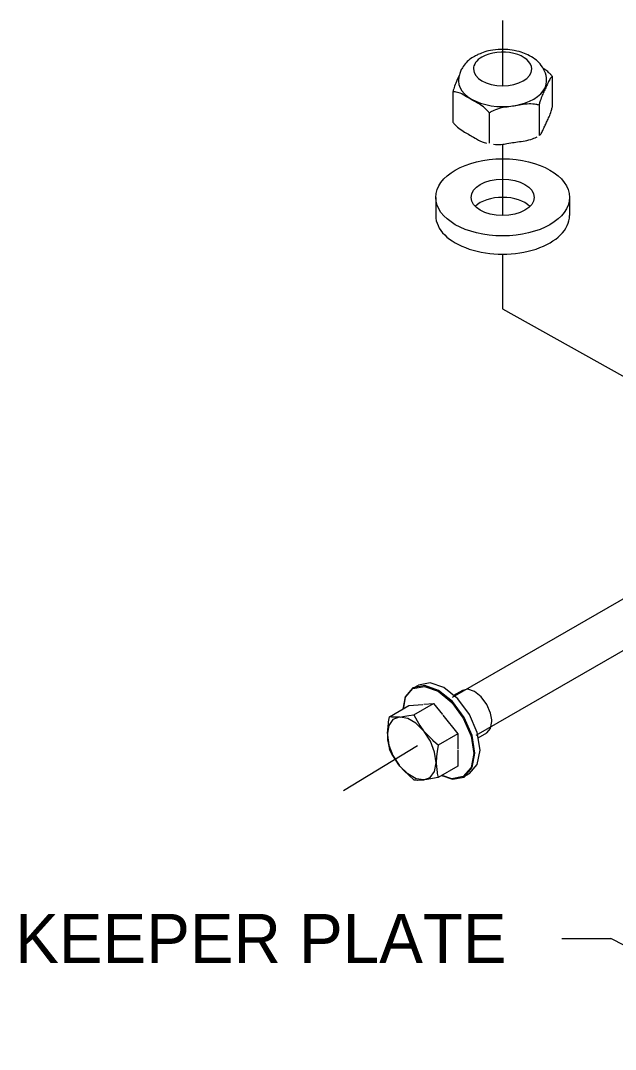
# Model space of a CAD drawing. Extents: x 99862 to 103151, y 99997 to 117076.
# Drawn here: x 101413.6 to 101608, y 116157.4 to 116493.6 of the extents above; entities that cross this region are included whole.
import ezdxf

# ---------------------------------------------------------------- set-up
doc = ezdxf.new("R2010")
doc.units = 0
for name, color, linetype in [('Level 12', 7, 'Continuous'), ('Level 13', 7, 'Continuous'), ('Level 15', 7, 'Continuous'), ('Level 20', 7, 'Continuous'), ('Level 3', 7, 'Continuous'), ('Level 5', 7, 'Continuous'), ('Level 9', 7, 'Continuous')]:
    doc.layers.add(name, color=color, linetype=linetype)

msp = doc.modelspace()

# ---------------------------------------------------------------- linework, layer by layer
at = {"layer": 'Level 12'}
for p, q in [((101587.37, 116465.38), (101587.37, 116475.29)), ((101554.87, 116470.27), (101554.87, 116460.36)), ((101583.02, 116465.91), (101583.02, 116456)), ((101566.77, 116463.4), (101566.77, 116453.49)), ((101549.27, 116435.8), (101549.27, 116429.85)), ((101592.97, 116435.8), (101592.97, 116429.85))]:
    msp.add_line(p, q, dxfattribs=at)
for centre, major_axis, start_param, end_param in [((101571.12, 116477.74), (9.54, 0), 2.356194, 3.141593), ((101571.12, 116477.74), (9.54, 0), 6.283185, 8.63938), ((101571.12, 116477.74), (9.54, 0), 3.141593, 6.283185), ((101571.12, 116473.77), (-14.39, 0), 0, 3.141593), ((101571.12, 116429.85), (-10.32, 0), 3.664192, 5.760586), ((101571.12, 116429.85), (-21.85, 0), 0, 3.141593)]:
    msp.add_ellipse(centre, major_axis=major_axis, ratio=0.57735, start_param=start_param, end_param=end_param, dxfattribs=at)
for major_axis in [(-21.85, 0), (-10.32, 0)]:
    msp.add_ellipse((101571.12, 116435.8), major_axis=major_axis, ratio=0.57735, dxfattribs=at)
for points in [[(101585.51, 116473.77), (101585.51, 116475.3), (101584.96, 116477.05), (101583.29, 116479.65), (101581.88, 116480.92), (101579.19, 116482.53), (101577.46, 116483.21), (101574.01, 116484.03), (101571.64, 116484.22), (101567.64, 116483.95), (101565.34, 116483.43), (101563.06, 116482.46), (101562.44, 116482.16), (101560.6, 116481.09), (101559.23, 116479.92), (101557.85, 116478), (101557.37, 116477.06), (101556.87, 116475.48), (101556.73, 116474.55), (101556.73, 116473.77)], [(101587.37, 116475.29), (101587.11, 116475.64), (101586.81, 116475.97), (101585.87, 116476.88), (101585.14, 116477.44), (101584.38, 116477.94)], [(101556.99, 116475.82), (101556.41, 116474.57), (101555.72, 116473.15), (101555.08, 116471.06), (101554.97, 116470.67), (101554.87, 116470.27)], [(101587.37, 116475.29), (101587.27, 116475.29), (101587.16, 116475.2), (101586.5, 116474.49), (101585.79, 116472.87), (101585.19, 116471.59), (101584.6, 116470.31), (101583.88, 116468.86), (101583.22, 116466.71), (101583.11, 116466.31), (101583.02, 116465.91)], [(101566.77, 116463.4), (101566.51, 116463.74), (101566.2, 116464.08), (101564.39, 116465.84), (101562.44, 116466.88), (101560.82, 116467.82), (101559.19, 116468.76), (101557.25, 116469.97), (101555.44, 116470.29), (101555.13, 116470.31), (101554.87, 116470.27)], [(101583.02, 116465.91), (101582.66, 116466.05), (101582.25, 116466.14), (101579.77, 116466.48), (101577.11, 116465.99), (101574.89, 116465.64), (101572.67, 116465.3), (101570.01, 116464.97), (101567.54, 116463.87), (101567.12, 116463.65), (101566.77, 116463.4)], [(101583.14, 116456.05), (101583.2, 116456.09), (101583.26, 116456.14), (101583.88, 116456.8), (101584.6, 116458.42), (101585.19, 116459.71), (101585.79, 116460.99), (101586.5, 116462.44), (101587.16, 116464.59), (101587.27, 116464.98), (101587.37, 116465.38)], [(101554.87, 116460.36), (101555.13, 116460.01), (101555.44, 116459.68), (101557.25, 116457.91), (101559.19, 116456.87), (101560.82, 116455.94), (101562.41, 116455.02), (101564.31, 116453.84), (101565.83, 116453.53)], [(101568.11, 116453.18), (101570.17, 116452.95), (101572.74, 116453.43), (101574.89, 116453.76), (101577.11, 116454.1), (101579.77, 116454.43), (101582.05, 116455.44), (101582.23, 116455.53), (101582.42, 116455.63)]]:
    msp.add_open_spline(points, degree=3, dxfattribs=at)
at = {"layer": 'Level 13'}
for p, q in [((101554.8, 116272.49), (101645.58, 116324.9)), ((101562.5, 116260.11), (101652.86, 116312.28))]:
    msp.add_line(p, q, dxfattribs=at)
at = {"layer": 'Level 15'}
for p, q in [((101571.12, 116493.56), (101571.12, 116472.23)), ((101571.12, 116465.46), (101571.12, 116465.01)), ((101571.12, 116453.22), (101571.12, 116429.84)), ((101571.12, 116417.24), (101571.12, 116399.4)), ((101519.18, 116241.97), (101543.31, 116256.68)), ((101590.44, 116193.67), (101606.44, 116193.67)), ((101676.74, 116157.42), (101606.44, 116193.67))]:
    msp.add_line(p, q, dxfattribs=at)
msp.add_lwpolyline([(101571.12, 116399.4), (101707.38, 116323.31)], dxfattribs=at)
at = {"layer": 'Level 3'}
for p, q in [((101539.31, 116272.38), (101541.83, 116275.29)), ((101541.86, 116275.23), (101541.83, 116275.29)), ((101545.62, 116275.95), (101545.61, 116276.01)), ((101550.06, 116274.39), (101550.06, 116274.44)), ((101539.28, 116272.64), (101538.5, 116268.57)), ((101554.49, 116270.77), (101554.51, 116270.81)), ((101541.71, 116266.71), (101541.82, 116266.67)), ((101558.25, 116265.66), (101558.28, 116265.68)), ((101560.76, 116259.83), (101560.81, 116259.82)), ((101561.65, 116254.16), (101561.69, 116254.13)), ((101558.55, 116246.42), (101561.11, 116249.38)), ((101554.49, 116245.91), (101554.51, 116245.85)), ((101558.25, 116246.63), (101558.28, 116246.57))]:
    msp.add_line(p, q, dxfattribs=at)
for points in [[(101545.67, 116276.33), (101541.84, 116275.6), (101541.84, 116275.59)], [(101550.2, 116274.73), (101545.67, 116276.33), (101545.67, 116276.33)], [(101541.84, 116275.6), (101539.28, 116272.64), (101539.28, 116272.64)], [(101541.86, 116275.22), (101541.83, 116275.29), (101545.61, 116276.01)], [(101545.62, 116275.95), (101545.61, 116276.01), (101550.06, 116274.44)], [(101550.05, 116274.39), (101550.06, 116274.44), (101554.51, 116270.81)], [(101554.72, 116271.05), (101550.2, 116274.73), (101550.2, 116274.73)], [(101539.35, 116272.32), (101539.31, 116272.38), (101538.6, 116268.63)], [(101554.48, 116270.78), (101554.51, 116270.81), (101558.28, 116265.68)], [(101558.55, 116265.83), (101554.72, 116271.05), (101554.72, 116271.05)], [(101558.24, 116265.67), (101558.28, 116265.68), (101560.81, 116259.82)], [(101560.76, 116259.84), (101560.81, 116259.82), (101561.69, 116254.13)], [(101561.64, 116254.17), (101561.69, 116254.13), (101560.81, 116249.48)], [(101561.97, 116254.11), (101561.98, 116254.11), (101561.98, 116254.11), (101562.01, 116254.1)], [(101560.81, 116249.48), (101558.28, 116246.57)], [(101551.22, 116246.92), (101554.72, 116245.68), (101554.72, 116245.69)], [(101554.5, 116245.91), (101554.51, 116245.85), (101551.32, 116246.97)], [(101558.26, 116246.63), (101558.28, 116246.57), (101554.51, 116245.85)], [(101554.72, 116245.68), (101558.55, 116246.42), (101558.55, 116246.42)]]:
    msp.add_lwpolyline(points, dxfattribs=at)
at = {"layer": 'Level 5'}
for p, q in [((101542.23, 116275.67), (101543.6, 116276.46)), ((101561.04, 116249.41), (101561.05, 116249.43))]:
    msp.add_line(p, q, dxfattribs=at)
for points in [[(101558.82, 116246.72), (101560.28, 116247.57), (101562.84, 116250.51), (101563.74, 116255.21), (101562.84, 116260.94), (101560.28, 116266.83), (101556.46, 116271.99), (101551.94, 116275.64), (101547.43, 116277.21), (101543.6, 116276.46)], [(101563.1, 116259.24), (101565.95, 116260.89), (101567.18, 116262.3), (101567.61, 116264.54), (101567.59, 116265.1), (101567.18, 116267.28), (101565.95, 116270.11), (101564.12, 116272.58), (101561.96, 116274.32), (101559.8, 116275.07), (101557.97, 116274.71), (101555.12, 116273.07)], [(101561.14, 116249.53), (101561.15, 116249.54), (101562.04, 116254.23), (101561.15, 116259.96), (101558.59, 116265.85), (101554.76, 116271.02), (101554.23, 116271.45)], [(101551.21, 116246.91), (101551.23, 116246.9), (101551.52, 116246.81)]]:
    msp.add_lwpolyline(points, dxfattribs=at)
at = {"layer": 'Level 9'}
msp.add_line((101542.13, 116266.78), (101548.49, 116270.46), dxfattribs=at)
msp.add_line((101542.13, 116266.78), (101548.49, 116270.46), dxfattribs=at)
for points in [[(101533.46, 116260.6), (101533.46, 116260.72), (101533.8, 116264), (101533.84, 116264.43), (101534.17, 116266.07), (101540.53, 116269.75), (101545.01, 116270.15)], [(101533.46, 116260.6), (101533.46, 116260.72), (101533.8, 116264), (101533.84, 116264.43), (101534.17, 116266.07), (101540.53, 116269.75), (101545.01, 116270.15)], [(101545.42, 116270.18), (101548.49, 116270.46), (101551.43, 116266.8)], [(101545.42, 116270.18), (101548.49, 116270.46), (101551.43, 116266.8)], [(101537.61, 116266.03), (101537.27, 116266), (101536.81, 116265.97), (101535.21, 116265.99), (101534.82, 116265.99), (101534.17, 116266.07)], [(101537.61, 116266.03), (101537.27, 116266), (101536.81, 116265.97), (101535.21, 116265.99), (101534.82, 116265.99), (101534.17, 116266.07)], [(101544.07, 116263.25), (101545.31, 116261.54), (101542.81, 116264.01), (101540.11, 116265.58), (101537.61, 116266.03), (101538.51, 116266.14), (101540.5, 116266.49), (101542.13, 116266.78), (101543.22, 116264.79), (101544.07, 116263.25)], [(101544.07, 116263.25), (101545.31, 116261.54), (101542.81, 116264.01), (101540.11, 116265.58), (101537.61, 116266.03), (101538.51, 116266.14), (101540.5, 116266.49), (101542.13, 116266.78), (101543.22, 116264.79), (101544.07, 116263.25)], [(101551.58, 116266.62), (101556.46, 116260.55), (101556.46, 116255.67)], [(101551.58, 116266.62), (101556.46, 116260.55), (101556.46, 116255.67)], [(101537.27, 116266), (101535.29, 116265.17), (101533.96, 116263.28), (101533.46, 116260.6)], [(101537.27, 116266), (101535.29, 116265.17), (101533.96, 116263.28), (101533.46, 116260.6)], [(101533.46, 116260.6), (101533.46, 116260.1), (101533.55, 116258.53), (101533.84, 116257.08), (101534.17, 116255.46)], [(101533.46, 116260.6), (101533.46, 116260.1), (101533.55, 116258.53), (101533.84, 116257.08), (101534.17, 116255.46)], [(101533.46, 116260.1), (101533.96, 116256.84), (101535.3, 116253.4), (101537.29, 116250.28)], [(101533.46, 116260.1), (101533.96, 116256.84), (101535.3, 116253.4), (101537.29, 116250.28)], [(101556.46, 116260.55), (101550.09, 116256.88), (101548.68, 116258.05), (101548.29, 116258.44), (101545.68, 116261.08), (101545.49, 116261.31), (101545.31, 116261.54)], [(101556.46, 116260.55), (101550.09, 116256.88), (101548.68, 116258.05), (101548.29, 116258.44), (101545.68, 116261.08), (101545.49, 116261.31), (101545.31, 116261.54)], [(101545.4, 116245.5), (101547.46, 116246.29), (101548.88, 116248.24), (101549.38, 116251.1), (101548.91, 116254.54), (101547.53, 116258.12), (101545.49, 116261.31)], [(101545.4, 116245.5), (101547.46, 116246.29), (101548.88, 116248.24), (101549.38, 116251.1), (101548.91, 116254.54), (101547.53, 116258.12), (101545.49, 116261.31)], [(101550.09, 116256.88), (101549.74, 116254.72), (101549.48, 116253.17), (101549.4, 116251.11), (101549.38, 116250.8), (101549.72, 116247.9), (101549.77, 116247.53), (101550.09, 116246.27)], [(101550.09, 116256.88), (101549.74, 116254.72), (101549.48, 116253.17), (101549.4, 116251.11), (101549.38, 116250.8), (101549.72, 116247.9), (101549.77, 116247.53), (101550.09, 116246.27)], [(101537.58, 116249.92), (101537.29, 116250.28), (101537.17, 116250.44), (101535.22, 116253.47), (101534.94, 116253.91), (101534.17, 116255.46)], [(101537.58, 116249.92), (101537.29, 116250.28), (101537.17, 116250.44), (101535.22, 116253.47), (101534.94, 116253.91), (101534.17, 116255.46)], [(101556.46, 116255.27), (101556.46, 116249.94), (101550.09, 116246.27), (101548.26, 116245.94), (101546.47, 116245.62), (101545.4, 116245.5)], [(101556.46, 116255.27), (101556.46, 116249.94), (101550.09, 116246.27), (101548.26, 116245.94), (101546.47, 116245.62), (101545.4, 116245.5)], [(101537.58, 116249.92), (101538.95, 116248.39), (101540.48, 116247.03), (101542.13, 116245.55), (101542.78, 116245.47), (101543.24, 116245.44), (101543.27, 116245.44), (101545.4, 116245.5)], [(101545.4, 116245.5), (101542.87, 116245.88), (101540.13, 116247.43), (101537.58, 116249.92)], [(101537.58, 116249.92), (101538.95, 116248.39), (101540.48, 116247.03), (101542.13, 116245.55), (101542.78, 116245.47), (101543.24, 116245.44), (101543.27, 116245.44), (101545.4, 116245.5)], [(101545.4, 116245.5), (101542.87, 116245.88), (101540.13, 116247.43), (101537.58, 116249.92)]]:
    msp.add_lwpolyline(points, dxfattribs=at)

# ---------------------------------------------------------------- texts
at = {"layer": 'Level 20'}
msp.add_text('KEEPER PLATE', height=16, dxfattribs=at).set_placement((101411.88, 116185.67))

doc.saveas('drawing.dxf')
